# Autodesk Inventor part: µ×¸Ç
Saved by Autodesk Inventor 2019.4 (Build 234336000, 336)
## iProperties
Created: 2020-05
Part Number: µ×¸Ç
Material: Generic
Document SubType Name: Modeling
Designer: Administrator
Density: 1 g/cm^3
Appearance: Default
Title: µ×¸Ç
Author: Administrator
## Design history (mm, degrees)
feature "Body1"
body "Solid1"
